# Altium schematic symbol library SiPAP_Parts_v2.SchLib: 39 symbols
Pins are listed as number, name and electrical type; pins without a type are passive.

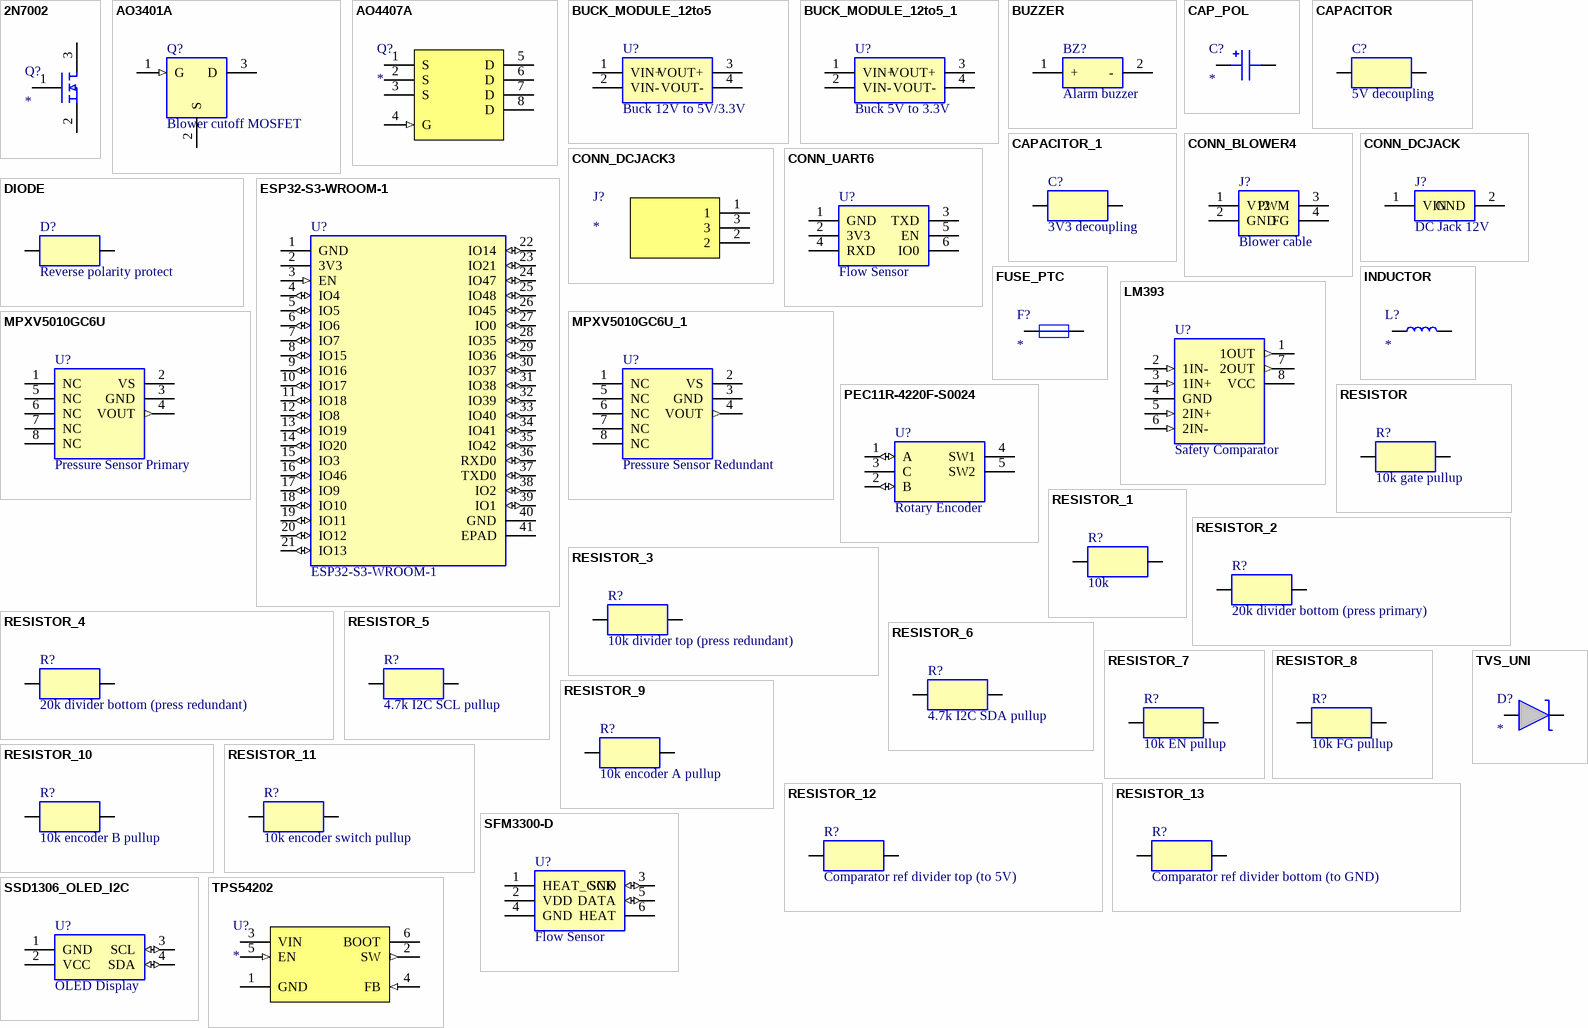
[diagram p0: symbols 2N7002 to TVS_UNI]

## 2N7002
designator Q?
N-channel MOSFET 60V 0.2A SOT-23 (Diodes 2N7002 DS11303 p1: 1=G 2=S 3=D)
footprint SOT-23
pins: 1 G, 2 S, 3 D

## AO3401A
designator Q?, comment Blower cutoff MOSFET
Alpha&Omega AO3401A P-channel MOSFET, SOT-23 (AOS datasheet)
footprint SOT-23
pins: 1 G (in), 2 S, 3 D

## AO4407A
designator Q?
AOS AO4407A P-channel MOSFET -30V -12A, SOIC-8 (S=1,2,3 G=4 D=5-8, datasheet Rev 11.1 p1 top view)
footprint SOIC-8
pins: 1 S, 2 S, 3 S, 4 G (in), 5 D, 6 D, 7 D, 8 D

## BUCK_MODULE_12to5
designator U?, comment Buck 12V to 5V/3.3V
Generic DC-DC buck converter module (e.g. MP1584EN based), 4-pin VIN/VOUT
footprint CONN_HEADER_4
pins: 1 VIN+ (power), 2 VIN- (power), 3 VOUT+ (power), 4 VOUT- (power)

## BUCK_MODULE_12to5_1
designator U?, comment Buck 5V to 3.3V
Generic DC-DC buck converter module (e.g. MP1584EN based), 4-pin VIN/VOUT
footprint CONN_HEADER_4
pins: 1 VIN+ (power), 2 VIN- (power), 3 VOUT+ (power), 4 VOUT- (power)

## BUZZER
designator BZ?, comment Alarm buzzer
Generic piezo buzzer, 2-pin
footprint BUZZER_TDK_PS1240
pins: 1 +, 2 -

## CAP_POL
designator C?
Polarized capacitor (aluminium electrolytic), pin 1 = +
footprint CAP_RAD_D8_P3.5
pins: 1, 2

## CAPACITOR
designator C?, comment 5V decoupling
Generic capacitor, 2-pin
footprint R_0805
pins: 1, 2

## CAPACITOR_1
designator C?, comment 3V3 decoupling
Generic capacitor, 2-pin
footprint R_0805
pins: 1, 2

## CONN_BLOWER4
designator J?, comment Blower cable
4-pin blower cable connector: 12V, GND, PWM, FG
footprint CONN_HEADER_4_2X2
pins: 1 V12, 2 GND, 3 PWM, 4 FG

## CONN_DCJACK
designator J?, comment DC Jack 12V
DC barrel jack 5.5x2.1mm, 2-pin (VIN, GND)
footprint DCJACK_THT_2PIN
pins: 1 VIN, 2 GND

## CONN_DCJACK3
designator J?
DC power jack 3-pin (Same Sky PJ-102AH): 1 centre pin (+), 2 sleeve, 3 switch
footprint CUI_PJ-102AH
pins: 1, 2, 3

## CONN_UART6
designator U?, comment Flow Sensor
6-pin 2.54mm programming header (USB-UART): GND 3V3 TXD RXD EN IO0
footprint CONN_HEADER_6
pins: 1 GND, 2 3V3, 3 TXD, 4 RXD, 5 EN, 6 IO0

## DIODE
designator D?, comment Reverse polarity protect
Generic diode, 2-pin (A=anode, K=cathode)
footprint DIOM_SMC_DO-214AB
pins: 1 A, 2 K

## ESP32-S3-WROOM-1
designator U?
Espressif ESP32-S3-WROOM-1 WiFi+BLE module, 41 pins (datasheet v1.8)
footprint ESP32-S3-WROOM-1_DS
pins: 1 GND (power), 2 3V3 (power), 3 EN (in), 4 IO4 (io), 5 IO5 (io), 6 IO6 (io), 7 IO7 (io), 8 IO15 (io), 9 IO16 (io), 10 IO17 (io), 11 IO18 (io), 12 IO8 (io), 13 IO19 (io), 14 IO20 (io), 15 IO3 (io), 16 IO46 (io), 17 IO9 (io), 18 IO10 (io), 19 IO11 (io), 20 IO12 (io), 21 IO13 (io), 22 IO14 (io), 23 IO21 (io), 24 IO47 (io), 25 IO48 (io), 26 IO45 (io), 27 IO0 (io), 28 IO35 (io), 29 IO36 (io), 30 IO37 (io), 31 IO38 (io), 32 IO39 (io), 33 IO40 (io), 34 IO41 (io), 35 IO42 (io), 36 RXD0 (io), 37 TXD0 (io), 38 IO2 (io), 39 IO1 (io), 40 GND (power), 41 EPAD (power)

## FUSE_PTC
designator F?
Resettable PTC fuse (Bourns MF-R300)
footprint PTC_RADIAL_MF-R300
pins: 1, 2

## INDUCTOR
designator L?
Power inductor (Bourns SRN6045TA)
footprint IND_BOURNS_SRN6045TA
pins: 1, 2

## LM393
designator U?, comment Safety Comparator
Dual comparator, DIP-8/SOIC-8 (TI datasheet SLCS006)
footprint SOIC-8
pins: 1 1OUT (out), 2 1IN- (in), 3 1IN+ (in), 4 GND (power), 5 2IN+ (in), 6 2IN- (in), 7 2OUT (out), 8 VCC (power)

## MPXV5010GC6U
designator U?, comment Pressure Sensor Primary
NXP/Motorola MPXV5010GC6U pressure sensor, SOP-8 (Case 482A), 0-10kPa analog output
footprint MPXV5010GC6U_482A
pins: 1 NC, 2 VS (power), 3 GND (power), 4 VOUT (out), 5 NC, 6 NC, 7 NC, 8 NC

## MPXV5010GC6U_1
designator U?, comment Pressure Sensor Redundant
NXP/Motorola MPXV5010GC6U pressure sensor, SOP-8 (Case 482A), 0-10kPa analog output
footprint MPXV5010GC6U_482A
pins: 1 NC, 2 VS (power), 3 GND (power), 4 VOUT (out), 5 NC, 6 NC, 7 NC, 8 NC

## PEC11R-4220F-S0024
designator U?, comment Rotary Encoder
Bourns PEC11R rotary encoder w/ push switch, 5 terminals (Bourns datasheet Rev 04/26)
footprint PEC11R-4220F-S0024
pins: 1 A (io), 2 B (io), 3 C, 4 SW1, 5 SW2

## RESISTOR
designator R?, comment 10k gate pullup
Generic resistor, 2-pin
footprint R_0805
pins: 1, 2

## RESISTOR_1
designator R?, comment 10k
Generic resistor, 2-pin
footprint R_0805
pins: 1, 2

## RESISTOR_2
designator R?, comment 20k divider bottom (press primary)
Generic resistor, 2-pin
footprint R_0805
pins: 1, 2

## RESISTOR_3
designator R?, comment 10k divider top (press redundant)
Generic resistor, 2-pin
footprint R_0805
pins: 1, 2

## RESISTOR_4
designator R?, comment 20k divider bottom (press redundant)
Generic resistor, 2-pin
footprint R_0805
pins: 1, 2

## RESISTOR_5
designator R?, comment 4.7k I2C SCL pullup
Generic resistor, 2-pin
footprint R_0805
pins: 1, 2

## RESISTOR_6
designator R?, comment 4.7k I2C SDA pullup
Generic resistor, 2-pin
footprint R_0805
pins: 1, 2

## RESISTOR_7
designator R?, comment 10k EN pullup
Generic resistor, 2-pin
footprint R_0805
pins: 1, 2

## RESISTOR_8
designator R?, comment 10k FG pullup
Generic resistor, 2-pin
footprint R_0805
pins: 1, 2

## RESISTOR_9
designator R?, comment 10k encoder A pullup
Generic resistor, 2-pin
footprint R_0805
pins: 1, 2

## RESISTOR_10
designator R?, comment 10k encoder B pullup
Generic resistor, 2-pin
footprint R_0805
pins: 1, 2

## RESISTOR_11
designator R?, comment 10k encoder switch pullup
Generic resistor, 2-pin
footprint R_0805
pins: 1, 2

## RESISTOR_12
designator R?, comment Comparator ref divider top (to 5V)
Generic resistor, 2-pin
footprint R_0805
pins: 1, 2

## RESISTOR_13
designator R?, comment Comparator ref divider bottom (to GND)
Generic resistor, 2-pin
footprint R_0805
pins: 1, 2

## SFM3300-D
designator U?, comment Flow Sensor
Sensirion SFM3300-D digital flow meter, I2C addr 0x40, 6-pad connector (Datasheet D1 v1.4)
footprint CONN_HEADER_6
pins: 1 HEAT_GND (power), 2 VDD (power), 3 SCK (io), 4 GND (power), 5 DATA (io), 6 HEAT

## SSD1306_OLED_I2C
designator U?, comment OLED Display
0.96in 128x64 I2C OLED module, 4-pin (GND,VCC,SCL,SDA), addr 0x3C
footprint CONN_HEADER_4
pins: 1 GND (power), 2 VCC (power), 3 SCL (io), 4 SDA (io)

## TPS54202
designator U?
TI TPS54202 4.5-28V 2A synchronous buck, SOT-23-6 (DDC)
footprint TI_DDC0006A_SOT23-6
pins: 1 GND (power), 2 SW (out), 3 VIN (power), 4 FB (in), 5 EN (in), 6 BOOT

## TVS_UNI
designator D?
Unidirectional TVS (Bourns SMBJ15A), pin1 = cathode
footprint DIOM_SMB_DO-214AA_BOURNS
pins: 1 K, 2 A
